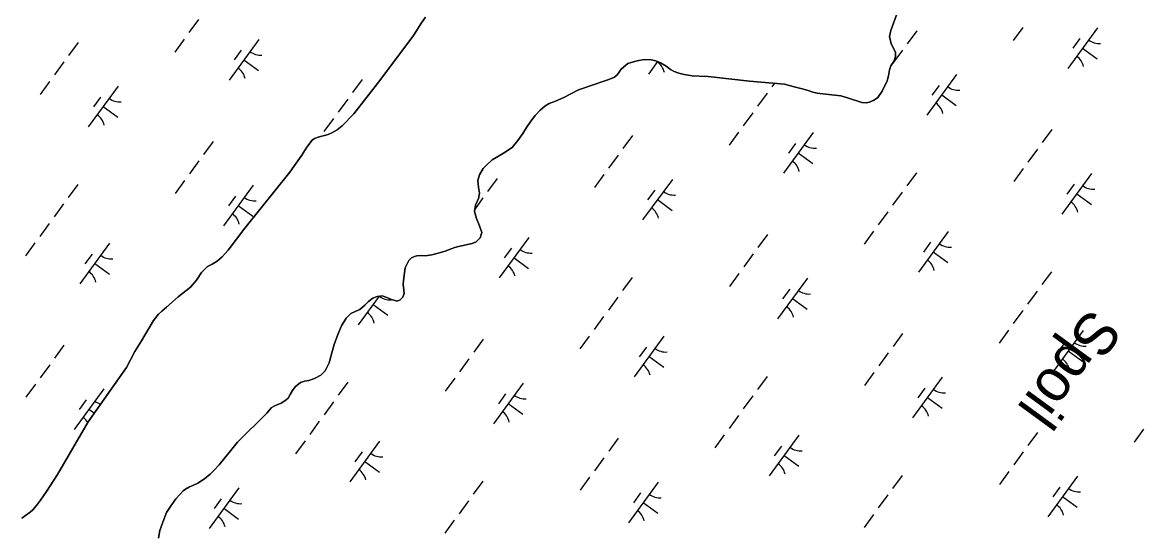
# Model space of a CAD drawing. Extents: x 3905714 to 3926767, y 183354 to 205755.
# Drawn here: x 3912781 to 3913896, y 191209 to 191717 of the extents above; entities that cross this region are included whole.
import ezdxf

# ---------------------------------------------------------------- set-up
doc = ezdxf.new("R2010")
doc.units = 0
for name, color, linetype in [('V-CHAN-SPOL', 7, 'Continuous'), ('V-TOPO-SHOR', 7, 'Continuous'), ('V-WETL-SWMP', 7, 'Continuous')]:
    doc.layers.add(name, color=color, linetype=linetype)

msp = doc.modelspace()

# ---------------------------------------------------------------- linework, layer by layer
at = {"layer": 'V-TOPO-SHOR'}
for points in [[(3913333.9, 191649.9), (3913350.5, 191655.6), (3913358.3, 191658.3), (3913364.2, 191660.3), (3913369.7, 191662.7), (3913372.4, 191665), (3913374.3, 191667.5), (3913376.2, 191670.1), (3913378.7, 191672.7), (3913383.2, 191676.1), (3913386.5, 191677.3), (3913392.5, 191678.8), (3913399.3, 191680.1), (3913406.1, 191680), (3913411, 191678.8), (3913415.5, 191677), (3913421.2, 191673.7), (3913425.5, 191670.4), (3913429.1, 191668.3), (3913433.6, 191666.7), (3913438.9, 191665.4), (3913446.9, 191664.1), (3913453.8, 191663.6), (3913463, 191663.2), (3913503.9, 191658.8), (3913538.7, 191655.7), (3913548.4, 191653.2), (3913556.2, 191651.1), (3913562.3, 191649.4), (3913567, 191647.8), (3913571.3, 191646.9), (3913576.7, 191646.2), (3913594.6, 191644.1), (3913601.5, 191642), (3913615.5, 191637.6), (3913620.1, 191637.2), (3913623, 191637.7), (3913627.2, 191639.3), (3913631.5, 191642.6), (3913635.7, 191648.6), (3913640.7, 191659.1), (3913642.2, 191664), (3913643.2, 191669.8), (3913644.5, 191674), (3913647.4, 191678.1), (3913649.2, 191683.3), (3913648.9, 191687.1), (3913646.8, 191692), (3913644.7, 191695.9), (3913643.2, 191702.9), (3913644.4, 191708.9), (3913655.4, 191739.1)], [(3912780.8, 191224.6), (3912784.5, 191227.3), (3912789, 191230.5), (3912791.6, 191232.8), (3912795.5, 191237.1), (3912799.5, 191242.5), (3912805.5, 191251.1), (3912816.4, 191267.8), (3912846.9, 191320.2), (3912884.7, 191374.1), (3912893.1, 191390), (3912899.6, 191400.7), (3912911.7, 191420.9), (3912916.6, 191427.1), (3912919.6, 191429.7), (3912920, 191430.3), (3912924.7, 191434), (3912936.3, 191444.3), (3912948.6, 191454.1), (3912954.3, 191461.1), (3912959.5, 191468.7), (3912965.2, 191474.5), (3912969.9, 191477), (3912975.1, 191479.8), (3912980, 191484.1), (3912985.8, 191490.8), (3913002.6, 191512.7), (3913047.3, 191568.1), (3913059, 191585.1), (3913064, 191593.2), (3913069.5, 191600.2), (3913071.6, 191601.8), (3913075.3, 191603.1), (3913078.8, 191604), (3913081.7, 191604.8), (3913085.1, 191605.6), (3913089, 191607.2), (3913094.3, 191610.4), (3913099.1, 191614.2), (3913110.9, 191626.1), (3913136.7, 191659.2), (3913169.9, 191704), (3913178.1, 191716.6), (3913181.9, 191722.4)], [(3913304.8, 191636.4), (3913311.3, 191638.9), (3913319.5, 191642.4), (3913333.9, 191649.9)], [(3912924.7, 191230.3), (3912929.2, 191237.2), (3912933.8, 191243.6), (3912937.8, 191248.1), (3912941.2, 191251.7), (3912943.5, 191253.4), (3912947.4, 191255.5), (3912950.8, 191257.1), (3912955.7, 191259.4), (3912962.3, 191263.5), (3912968, 191268.1), (3912972.1, 191272.2), (3912976.9, 191277.6), (3912995, 191300.1), (3913024.2, 191328.9), (3913027.8, 191333.3), (3913028.7, 191334), (3913030.8, 191335.6), (3913033.6, 191336.8), (3913036.1, 191337.8), (3913038.6, 191338.9), (3913042.2, 191341.1), (3913045.5, 191343.8), (3913047.4, 191347.4), (3913049.8, 191351.5), (3913052.6, 191355.1), (3913057.7, 191359.2), (3913061.7, 191360.6), (3913065.9, 191361.4), (3913071.8, 191363.4), (3913077.9, 191366.5), (3913082.2, 191370.9), (3913086.2, 191378.9), (3913088.8, 191388.8), (3913091.2, 191397), (3913095, 191407), (3913098.5, 191415.7), (3913103.1, 191423.1), (3913107.7, 191427.7), (3913112.2, 191429.7), (3913116.8, 191431.8), (3913121.6, 191436.1), (3913125.5, 191439.9), (3913129.5, 191443.1), (3913134, 191444.7), (3913138.9, 191445.5), (3913143.6, 191443.6), (3913148.1, 191441.7), (3913153.8, 191440.1), (3913156.8, 191441.5), (3913159.3, 191444), (3913160.9, 191447.6), (3913160.5, 191451.2), (3913159.8, 191456.6), (3913160.2, 191460.7), (3913161.9, 191473.3), (3913165.5, 191480.6), (3913168, 191483.3), (3913170.9, 191484.6), (3913173.5, 191485.2), (3913176.7, 191485.4), (3913181.8, 191485.3), (3913188.3, 191486.2), (3913194.5, 191487.7), (3913201.6, 191489.8), (3913207.5, 191492), (3913211.2, 191493.5), (3913214.7, 191494.5), (3913228.3, 191497.3), (3913232.3, 191498.9), (3913236.4, 191503), (3913237.9, 191508.2), (3913235.7, 191514.9), (3913232.7, 191522.2), (3913230.7, 191529.1), (3913231.8, 191535.4), (3913234.6, 191542.2), (3913235.6, 191547.4), (3913234.8, 191553.4), (3913234.1, 191559.9), (3913235.5, 191565.6), (3913239.4, 191571.8), (3913242.9, 191575.7), (3913248.4, 191580.5), (3913254.4, 191584.2), (3913259.4, 191587.3), (3913268, 191592.9), (3913273.9, 191599.7), (3913278.8, 191606.8), (3913282.3, 191612.8), (3913286.7, 191618.8), (3913290.9, 191624.7), (3913295.9, 191629.7), (3913300.6, 191633.8), (3913304.8, 191636.4)], [(3912916.7, 191204.6), (3912918, 191212.4), (3912920.8, 191220.5), (3912924.7, 191230.3)]]:
    msp.add_lwpolyline(points, dxfattribs=at)
at = {"layer": 'V-WETL-SWMP'}
for p, q in [((3913655.4, 191739.1), (3913644.4, 191708.9)), ((3912956.4, 191719.8), (3912946.9, 191706.9)), ((3913181.9, 191722.4), (3913178.1, 191716.6)), ((3913178.1, 191716.6), (3913169.9, 191704)), ((3913644.4, 191708.9), (3913643.2, 191702.9)), ((3913670.1, 191708.8), (3913660.7, 191695.9)), ((3913775.6, 191712.1), (3913766.1, 191699.2)), ((3913849.7, 191711.8), (3913820.2, 191671.4)), ((3912836.8, 191697.2), (3912827.3, 191684.2)), ((3912942.2, 191700.4), (3912932.8, 191687.5)), ((3913016.4, 191700.1), (3912986.8, 191659.8)), ((3913169.9, 191704), (3913136.7, 191659.2)), ((3913643.2, 191702.9), (3913644.7, 191695.9)), ((3913832.3, 191701), (3913825.2, 191691.3)), ((3912998.9, 191689.3), (3912991.8, 191679.7)), ((3913644.7, 191695.9), (3913646.8, 191692)), ((3913656, 191689.4), (3913646.5, 191676.5)), ((3913646.8, 191692), (3913648.9, 191687.1)), ((3913648.9, 191687.1), (3913649.2, 191683.3)), ((3913835, 191691.6), (3913849.5, 191681)), ((3912822.6, 191677.8), (3912813.2, 191664.9)), ((3913001.6, 191679.9), (3913016.1, 191669.3)), ((3913383.2, 191676.1), (3913378.7, 191672.7)), ((3913386.5, 191677.3), (3913383.2, 191676.1)), ((3913392.5, 191678.8), (3913386.5, 191677.3)), ((3913399.3, 191680.1), (3913392.5, 191678.8)), ((3913406.1, 191680), (3913399.3, 191680.1)), ((3913412.7, 191678.1), (3913403.5, 191665.6)), ((3913411, 191678.8), (3913406.1, 191680)), ((3913415.5, 191677), (3913411, 191678.8)), ((3913421.2, 191673.7), (3913415.5, 191677)), ((3913425.5, 191670.4), (3913421.2, 191673.7)), ((3913644.5, 191674), (3913643.2, 191669.8)), ((3913647.4, 191678.1), (3913644.5, 191674)), ((3913649.2, 191683.3), (3913647.4, 191678.1)), ((3913369.7, 191662.7), (3913364.2, 191660.3)), ((3913372.4, 191665), (3913369.7, 191662.7)), ((3913374.3, 191667.5), (3913372.4, 191665)), ((3913376.2, 191670.1), (3913374.3, 191667.5)), ((3913378.7, 191672.7), (3913376.2, 191670.1)), ((3913429.1, 191668.3), (3913425.5, 191670.4)), ((3913433.6, 191666.7), (3913429.1, 191668.3)), ((3913438.9, 191665.4), (3913433.6, 191666.7)), ((3913446.9, 191664.1), (3913438.9, 191665.4)), ((3913453.8, 191663.6), (3913446.9, 191664.1)), ((3913463, 191663.2), (3913453.8, 191663.6)), ((3913503.9, 191658.8), (3913463, 191663.2)), ((3913642.2, 191664), (3913640.7, 191659.1)), ((3913643.2, 191669.8), (3913642.2, 191664)), ((3913709.8, 191665.2), (3913680.2, 191624.9)), ((3912808.4, 191658.4), (3912799, 191645.5)), ((3912876.4, 191653.6), (3912846.9, 191613.3)), ((3913118.9, 191660.2), (3913109.5, 191647.3)), ((3913136.7, 191659.2), (3913110.9, 191626.1)), ((3913350.5, 191655.6), (3913333.9, 191649.9)), ((3913358.3, 191658.3), (3913350.5, 191655.6)), ((3913364.2, 191660.3), (3913358.3, 191658.3)), ((3913538.7, 191655.7), (3913503.9, 191658.8)), ((3913528.7, 191656.6), (3913526.2, 191653.1)), ((3913548.4, 191653.2), (3913538.7, 191655.7)), ((3913556.2, 191651.1), (3913548.4, 191653.2)), ((3913640.7, 191659.1), (3913635.7, 191648.6)), ((3913692.3, 191654.5), (3913685.2, 191644.8)), ((3912859, 191642.8), (3912851.9, 191633.2)), ((3913104.8, 191640.9), (3913095.3, 191628)), ((3913319.5, 191642.4), (3913311.3, 191638.9)), ((3913333.9, 191649.9), (3913319.5, 191642.4)), ((3913521.4, 191646.7), (3913512, 191633.8)), ((3913562.3, 191649.4), (3913556.2, 191651.1)), ((3913567, 191647.8), (3913562.3, 191649.4)), ((3913571.3, 191646.9), (3913567, 191647.8)), ((3913576.7, 191646.2), (3913571.3, 191646.9)), ((3913594.6, 191644.1), (3913576.7, 191646.2)), ((3913601.5, 191642), (3913594.6, 191644.1)), ((3913615.5, 191637.6), (3913601.5, 191642)), ((3913631.5, 191642.6), (3913627.2, 191639.3)), ((3913635.7, 191648.6), (3913631.5, 191642.6)), ((3913695, 191645.1), (3913709.5, 191634.4)), ((3912861.7, 191633.4), (3912876.2, 191622.8)), ((3913295.9, 191629.7), (3913290.9, 191624.7)), ((3913300.6, 191633.8), (3913295.9, 191629.7)), ((3913304.8, 191636.4), (3913300.6, 191633.8)), ((3913311.3, 191638.9), (3913304.8, 191636.4)), ((3913620.1, 191637.2), (3913615.5, 191637.6)), ((3913623, 191637.7), (3913620.1, 191637.2)), ((3913627.2, 191639.3), (3913623, 191637.7)), ((3913090.6, 191621.5), (3913081.1, 191608.6)), ((3913110.9, 191626.1), (3913099.1, 191614.2)), ((3913286.7, 191618.8), (3913282.3, 191612.8)), ((3913290.9, 191624.7), (3913286.7, 191618.8)), ((3913507.2, 191627.3), (3913497.8, 191614.4)), ((3913089, 191607.2), (3913085.1, 191605.6)), ((3913094.3, 191610.4), (3913089, 191607.2)), ((3913099.1, 191614.2), (3913094.3, 191610.4)), ((3913282.3, 191612.8), (3913278.8, 191606.8)), ((3913493.1, 191608), (3913483.6, 191595.1)), ((3913567.2, 191607.6), (3913537.7, 191567.3)), ((3913804.3, 191610.5), (3913794.9, 191597.6)), ((3912971, 191598.8), (3912961.5, 191585.9)), ((3913069.5, 191600.2), (3913064, 191593.2)), ((3913071.6, 191601.8), (3913069.5, 191600.2)), ((3913075.3, 191603.1), (3913071.6, 191601.8)), ((3913078.8, 191604), (3913075.3, 191603.1)), ((3913081.7, 191604.8), (3913078.8, 191604)), ((3913085.1, 191605.6), (3913081.7, 191604.8)), ((3913273.9, 191599.7), (3913268, 191592.9)), ((3913278.8, 191606.8), (3913273.9, 191599.7)), ((3913387.6, 191604.7), (3913378.2, 191591.8)), ((3913549.8, 191596.9), (3913542.7, 191587.2)), ((3913059, 191585.1), (3913047.3, 191568.1)), ((3913064, 191593.2), (3913059, 191585.1)), ((3913259.4, 191587.3), (3913254.4, 191584.2)), ((3913268, 191592.9), (3913259.4, 191587.3)), ((3913373.5, 191585.3), (3913364, 191572.4)), ((3913552.5, 191587.5), (3913567, 191576.8)), ((3913790.1, 191591.1), (3913780.7, 191578.2)), ((3912956.8, 191579.5), (3912947.3, 191566.6)), ((3913242.9, 191575.7), (3913239.4, 191571.8)), ((3913248.4, 191580.5), (3913242.9, 191575.7)), ((3913254.4, 191584.2), (3913248.4, 191580.5)), ((3913047.3, 191568.1), (3913002.6, 191512.7)), ((3913235.5, 191565.6), (3913234.1, 191559.9)), ((3913239.4, 191571.8), (3913235.5, 191565.6)), ((3913359.3, 191566), (3913349.8, 191553)), ((3913669.8, 191567.7), (3913660.3, 191554.8)), ((3913776, 191571.8), (3913766.5, 191558.9)), ((3913844, 191566.9), (3913814.4, 191526.6)), ((3912836.4, 191556.1), (3912827, 191543.2)), ((3912942.6, 191560.1), (3912933.2, 191547.2)), ((3913010.6, 191555.3), (3912981.1, 191515)), ((3913234.1, 191559.9), (3913234.8, 191553.4)), ((3913234.8, 191553.4), (3913235.6, 191547.4)), ((3913253.1, 191561.9), (3913243.7, 191549)), ((3913427.3, 191561.1), (3913397.7, 191520.8)), ((3913826.5, 191556.2), (3913819.4, 191546.5)), ((3912993.2, 191544.5), (3912986.1, 191534.8)), ((3913238.9, 191542.6), (3913231.2, 191532)), ((3913234.6, 191542.2), (3913231.8, 191535.4)), ((3913235.6, 191547.4), (3913234.6, 191542.2)), ((3913409.8, 191550.4), (3913402.7, 191540.7)), ((3913412.5, 191541), (3913427, 191530.3)), ((3913655.6, 191548.4), (3913646.2, 191535.5)), ((3913829.2, 191546.8), (3913843.7, 191536.1)), ((3912822.3, 191536.7), (3912812.8, 191523.8)), ((3912995.8, 191535.1), (3913010.4, 191524.5)), ((3913231.8, 191535.4), (3913230.7, 191529.1)), ((3913230.7, 191529.1), (3913232.7, 191522.2)), ((3913641.4, 191529), (3913632, 191516.1)), ((3913232.7, 191522.2), (3913235.7, 191514.9)), ((3912808.1, 191517.4), (3912798.6, 191504.5)), ((3913002.6, 191512.7), (3912985.8, 191490.8)), ((3913235.7, 191514.9), (3913237.9, 191508.2)), ((3913237.9, 191508.2), (3913236.4, 191503)), ((3913627.2, 191509.7), (3913617.8, 191496.7)), ((3913701.4, 191509.3), (3913671.9, 191469)), ((3912793.9, 191498), (3912784.4, 191485.1)), ((3912868.1, 191497.7), (3912838.5, 191457.3)), ((3913228.3, 191497.3), (3913214.7, 191494.5)), ((3913232.3, 191498.9), (3913228.3, 191497.3)), ((3913236.4, 191503), (3913232.3, 191498.9)), ((3913284.8, 191503.5), (3913255.2, 191463.2)), ((3913521.8, 191506.4), (3913512.4, 191493.5)), ((3913684, 191498.6), (3913676.9, 191488.9)), ((3912850.6, 191486.9), (3912843.5, 191477.2)), ((3912985.8, 191490.8), (3912980, 191484.1)), ((3913170.9, 191484.6), (3913168, 191483.3)), ((3913173.5, 191485.2), (3913170.9, 191484.6)), ((3913176.7, 191485.4), (3913173.5, 191485.2)), ((3913181.8, 191485.3), (3913176.7, 191485.4)), ((3913188.3, 191486.2), (3913181.8, 191485.3)), ((3913194.5, 191487.7), (3913188.3, 191486.2)), ((3913201.6, 191489.8), (3913194.5, 191487.7)), ((3913207.5, 191492), (3913201.6, 191489.8)), ((3913211.2, 191493.5), (3913207.5, 191492)), ((3913214.7, 191494.5), (3913211.2, 191493.5)), ((3913267.3, 191492.7), (3913260.2, 191483.1)), ((3913507.6, 191487), (3913498.2, 191474.1)), ((3913686.6, 191489.2), (3913701.2, 191478.5)), ((3912853.3, 191477.5), (3912867.8, 191466.9)), ((3912965.2, 191474.5), (3912959.5, 191468.7)), ((3912969.9, 191477), (3912965.2, 191474.5)), ((3912975.1, 191479.8), (3912969.9, 191477)), ((3912980, 191484.1), (3912975.1, 191479.8)), ((3913161.9, 191473.3), (3913160.2, 191460.7)), ((3913165.5, 191480.6), (3913161.9, 191473.3)), ((3913168, 191483.3), (3913165.5, 191480.6)), ((3913270, 191483.3), (3913284.5, 191472.7)), ((3912959.5, 191468.7), (3912954.3, 191461.1)), ((3913387.3, 191463.6), (3913377.8, 191450.7)), ((3913493.5, 191467.6), (3913484, 191454.7)), ((3913561.5, 191462.8), (3913531.9, 191422.5)), ((3913804, 191469.4), (3913794.5, 191456.5)), ((3912948.6, 191454.1), (3912936.3, 191444.3)), ((3912954.3, 191461.1), (3912948.6, 191454.1)), ((3913160.2, 191460.7), (3913159.8, 191456.6)), ((3913159.8, 191456.6), (3913160.5, 191451.2)), ((3913160.5, 191451.2), (3913160.9, 191447.6)), ((3913544, 191452), (3913536.9, 191442.4)), ((3912936.3, 191444.3), (3912924.7, 191434)), ((3913136, 191445), (3913115.2, 191416.7)), ((3913125.5, 191439.9), (3913121.6, 191436.1)), ((3913129.5, 191443.1), (3913125.5, 191439.9)), ((3913134, 191444.7), (3913129.5, 191443.1)), ((3913138.9, 191445.5), (3913134, 191444.7)), ((3913143.6, 191443.6), (3913138.9, 191445.5)), ((3913148.1, 191441.7), (3913143.6, 191443.6)), ((3913153.8, 191440.1), (3913148.1, 191441.7)), ((3913156.8, 191441.5), (3913153.8, 191440.1)), ((3913159.3, 191444), (3913156.8, 191441.5)), ((3913160.9, 191447.6), (3913159.3, 191444)), ((3913373.1, 191444.2), (3913363.7, 191431.3)), ((3913546.7, 191442.6), (3913561.2, 191432)), ((3913789.8, 191450.1), (3913780.3, 191437.2)), ((3912919.6, 191429.7), (3912916.6, 191427.1)), ((3912920, 191430.3), (3912919.6, 191429.7)), ((3912924.7, 191434), (3912920, 191430.3)), ((3913112.2, 191429.7), (3913107.7, 191427.7)), ((3913116.8, 191431.8), (3913112.2, 191429.7)), ((3913121.6, 191436.1), (3913116.8, 191431.8)), ((3913130, 191436.8), (3913144.5, 191426.2)), ((3913775.6, 191430.7), (3913766.1, 191417.8)), ((3912911.7, 191420.9), (3912899.6, 191400.7)), ((3912916.6, 191427.1), (3912911.7, 191420.9)), ((3913103.1, 191423.1), (3913098.5, 191415.7)), ((3913107.7, 191427.7), (3913103.1, 191423.1)), ((3913358.9, 191424.9), (3913349.5, 191412)), ((3913095, 191407), (3913091.2, 191397)), ((3913098.5, 191415.7), (3913095, 191407)), ((3913656, 191408.1), (3913646.6, 191395.2)), ((3913761.4, 191411.4), (3913752, 191398.4)), ((3913835.6, 191411), (3913806.1, 191370.7)), ((3912822.7, 191396.4), (3912813.2, 191383.5)), ((3912899.6, 191400.7), (3912893.1, 191390)), ((3913091.2, 191397), (3913088.8, 191388.8)), ((3913239.3, 191402.2), (3913229.9, 191389.3)), ((3913344.7, 191405.5), (3913335.3, 191392.6)), ((3913418.9, 191405.2), (3913389.4, 191364.9)), ((3913818.2, 191400.3), (3913811.1, 191390.6)), ((3912893.1, 191390), (3912884.7, 191374.1)), ((3913088.8, 191388.8), (3913086.2, 191378.9)), ((3913401.5, 191394.4), (3913394.4, 191384.8)), ((3913404.2, 191385), (3913418.7, 191374.4)), ((3913641.8, 191388.7), (3913632.4, 191375.8)), ((3913820.8, 191390.9), (3913835.3, 191380.2)), ((3912808.5, 191377), (3912799, 191364.1)), ((3912884.7, 191374.1), (3912846.9, 191320.2)), ((3913086.2, 191378.9), (3913082.2, 191370.9)), ((3913225.2, 191382.9), (3913215.7, 191370)), ((3913071.8, 191363.4), (3913065.9, 191361.4)), ((3913077.9, 191366.5), (3913071.8, 191363.4)), ((3913082.2, 191370.9), (3913077.9, 191366.5)), ((3913211, 191363.5), (3913201.5, 191350.6)), ((3913521.5, 191365.3), (3913512, 191352.4)), ((3913627.6, 191369.3), (3913618.2, 191356.4)), ((3913695.6, 191364.5), (3913666.1, 191324.2)), ((3912794.3, 191357.7), (3912784.8, 191344.8)), ((3912862.3, 191352.9), (3912832.8, 191312.5)), ((3913049.8, 191351.5), (3913047.4, 191347.4)), ((3913052.6, 191355.1), (3913049.8, 191351.5)), ((3913057.7, 191359.2), (3913052.6, 191355.1)), ((3913061.7, 191360.6), (3913057.7, 191359.2)), ((3913065.9, 191361.4), (3913061.7, 191360.6)), ((3913104.8, 191359.5), (3913095.3, 191346.6)), ((3913279, 191358.7), (3913249.4, 191318.3)), ((3913678.2, 191353.7), (3913671.1, 191344.1)), ((3912844.8, 191342.1), (3912837.8, 191332.4)), ((3913042.2, 191341.1), (3913038.6, 191338.9)), ((3913045.5, 191343.8), (3913042.2, 191341.1)), ((3913047.4, 191347.4), (3913045.5, 191343.8)), ((3913090.6, 191340.1), (3913081.2, 191327.2)), ((3913261.5, 191347.9), (3913254.4, 191338.2)), ((3913507.3, 191345.9), (3913497.8, 191333)), ((3913680.9, 191344.3), (3913695.4, 191333.7)), ((3912847.5, 191332.7), (3912852.9, 191328.7)), ((3913024.2, 191328.9), (3912995, 191300.1)), ((3913027.8, 191333.3), (3913024.2, 191328.9)), ((3913028.7, 191334), (3913027.8, 191333.3)), ((3913030.8, 191335.6), (3913028.7, 191334)), ((3913033.6, 191336.8), (3913030.8, 191335.6)), ((3913036.1, 191337.8), (3913033.6, 191336.8)), ((3913038.6, 191338.9), (3913036.1, 191337.8)), ((3913264.2, 191338.5), (3913278.7, 191327.9)), ((3912846.9, 191320.2), (3912816.4, 191267.8)), ((3913076.4, 191320.8), (3913067, 191307.8)), ((3913493.1, 191326.6), (3913483.7, 191313.7)), ((3913478.9, 191307.2), (3913469.5, 191294.3)), ((3913553.1, 191306.9), (3913523.6, 191266.6)), ((3913790.2, 191309.8), (3913780.7, 191296.8)), ((3913895.6, 191313), (3913886.1, 191300.1)), ((3912995, 191300.1), (3912976.9, 191277.6)), ((3913062.3, 191301.4), (3913052.8, 191288.5)), ((3913136.4, 191301.1), (3913106.9, 191260.7)), ((3913373.5, 191303.9), (3913364.1, 191291)), ((3913535.7, 191296.1), (3913528.6, 191286.4)), ((3913119, 191290.3), (3913111.9, 191280.6)), ((3913359.3, 191284.6), (3913349.9, 191271.7)), ((3913538.3, 191286.7), (3913552.9, 191276.1)), ((3913776, 191290.4), (3913766.5, 191277.5)), ((3912976.9, 191277.6), (3912972.1, 191272.2)), ((3913121.7, 191280.9), (3913136.2, 191270.3)), ((3912816.4, 191267.8), (3912805.5, 191251.1)), ((3912962.3, 191263.5), (3912955.7, 191259.4)), ((3912968, 191268.1), (3912962.3, 191263.5)), ((3912972.1, 191272.2), (3912968, 191268.1)), ((3913345.1, 191265.2), (3913335.7, 191252.3)), ((3913655.7, 191267), (3913646.2, 191254.1)), ((3913761.8, 191271), (3913752.4, 191258.1)), ((3913829.8, 191266.2), (3913800.3, 191225.9)), ((3912805.5, 191251.1), (3912799.5, 191242.5)), ((3912941.2, 191251.7), (3912937.8, 191248.1)), ((3912943.5, 191253.4), (3912941.2, 191251.7)), ((3912947.4, 191255.5), (3912943.5, 191253.4)), ((3912950.8, 191257.1), (3912947.4, 191255.5)), ((3912955.7, 191259.4), (3912950.8, 191257.1)), ((3912996.5, 191254.6), (3912966.9, 191214.2)), ((3913239, 191261.2), (3913229.5, 191248.3)), ((3913413.2, 191260.4), (3913383.6, 191220)), ((3913812.4, 191255.4), (3913805.3, 191245.8)), ((3912799.5, 191242.5), (3912795.5, 191237.1)), ((3912933.8, 191243.6), (3912929.2, 191237.2)), ((3912937.8, 191248.1), (3912933.8, 191243.6)), ((3912979, 191243.8), (3912971.9, 191234.1)), ((3913224.8, 191241.8), (3913215.3, 191228.9)), ((3913395.7, 191249.6), (3913388.6, 191239.9)), ((3913398.4, 191240.2), (3913412.9, 191229.6)), ((3913641.5, 191247.6), (3913632, 191234.7)), ((3913815.1, 191246), (3913829.6, 191235.4)), ((3912789, 191230.5), (3912784.5, 191227.3)), ((3912791.6, 191232.8), (3912789, 191230.5)), ((3912795.5, 191237.1), (3912791.6, 191232.8)), ((3912924.7, 191230.3), (3912920.8, 191220.5)), ((3912929.2, 191237.2), (3912924.7, 191230.3)), ((3912981.7, 191234.4), (3912996.2, 191223.7)), ((3913627.3, 191228.3), (3913617.8, 191215.4)), ((3912784.5, 191227.3), (3912780.8, 191224.6)), ((3912920.8, 191220.5), (3912918, 191212.4)), ((3913210.6, 191222.4), (3913201.2, 191209.5)), ((3912918, 191212.4), (3912916.7, 191204.6))]:
    msp.add_line(p, q, dxfattribs=at)
for centre, start, end in [((3913851.5, 191713.7), 233, 274.5436), ((3913018.1, 191702.1), 233, 274.5436), ((3913402.2, 191663.4), 13, 54.5436), ((3913818.8, 191669.2), 13, 54.5436), ((3912985.5, 191657.5), 13, 54.5436), ((3913711.5, 191667.2), 233, 274.5436), ((3912878.2, 191655.6), 233, 274.5436), ((3913678.9, 191622.7), 13, 54.5436), ((3912845.5, 191611), 13, 54.5436), ((3913569, 191609.6), 233, 274.5436), ((3913536.3, 191565), 13, 54.5436), ((3913845.7, 191568.9), 233, 274.5436), ((3913012.4, 191557.3), 233, 274.5436), ((3913429, 191563.1), 233, 274.5436), ((3913396.4, 191518.5), 13, 54.5436), ((3913813.1, 191524.4), 13, 54.5436), ((3912979.7, 191512.7), 13, 54.5436), ((3913703.2, 191511.3), 233, 274.5436), ((3912869.8, 191499.7), 233, 274.5436), ((3913286.5, 191505.5), 233, 274.5436), ((3913253.8, 191460.9), 13, 54.5436), ((3913670.5, 191466.7), 13, 54.5436), ((3912837.2, 191455.1), 13, 54.5436), ((3913146.5, 191459), 233, 274.5436), ((3913563.2, 191464.8), 233, 274.5436), ((3913113.9, 191414.4), 13, 54.5436), ((3913530.6, 191420.2), 13, 54.5436), ((3913837.3, 191413), 233, 274.5436), ((3913420.7, 191407.2), 233, 274.5436), ((3913388, 191362.6), 13, 54.5436), ((3913804.7, 191368.4), 13, 54.5436), ((3913697.4, 191366.5), 233, 274.5436), ((3912864, 191354.8), 233, 254.4065), ((3913280.7, 191360.7), 233, 274.5436), ((3913248.1, 191316.1), 13, 54.5436), ((3913664.7, 191321.9), 13, 54.5436), ((3912831.4, 191310.3), 31.2248, 54.5436), ((3913138.2, 191303), 233, 274.5436), ((3913554.9, 191308.9), 233, 274.5436), ((3913105.5, 191258.5), 13, 54.5436), ((3913522.2, 191264.3), 13, 54.5436), ((3913831.6, 191268.2), 233, 274.5436), ((3912998.2, 191256.5), 233, 274.5436), ((3913414.9, 191262.4), 233, 274.5436), ((3913382.2, 191217.8), 13, 54.5436), ((3913798.9, 191223.6), 13, 54.5436), ((3912965.6, 191212), 13, 54.5436)]:
    msp.add_arc(centre, 17.6, start, end, dxfattribs=at)

# ---------------------------------------------------------------- texts
at = {"layer": 'V-CHAN-SPOL'}
msp.add_text('Spoil', height=42, rotation=233.8714, dxfattribs=at).set_placement((3913842.4, 191434.9))

doc.saveas('drawing.dxf')
